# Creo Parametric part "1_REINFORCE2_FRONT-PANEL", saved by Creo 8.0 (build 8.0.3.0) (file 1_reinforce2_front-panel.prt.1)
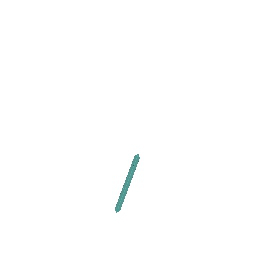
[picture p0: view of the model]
Units: millimeter Newton Second (mmNs); MM, TONNE, SECS

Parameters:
  SMT_DFLT_BEND_REL_LENGTH_TYPE = "Through All"

Other parameters: SMT_THICKNESS, SMT_PART_BEND_ALLOWANCE_FACTOR, SMT_DFLT_BEND_RADIUS, SMT_DFLT_BEND_ANGLE, SMT_DFLT_CRNR_REL_WIDTH, SMT_DFLT_CRNR_REL_DEPTH, SMT_DFLT_BEND_REL_WIDTH, SMT_DFLT_BEND_REL_DEPTH, SMT_DFLT_BEND_REL_LENGTH, SMT_DFLT_BEND_REL_ANGLE, SMT_GAP, SMT_DFLT_EDGE_TREA_WIDTH, SMT_DFLT_MITER_CUT_WIDTH, SMT_DFLT_MITER_CUT_OFFSET

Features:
  1. datum plane "DTM1"
  2. datum plane "DTM2"
  3. datum plane "DTM3"
  4. coordinate system
  5. protrusion
  6. round
  7. cut

Other named items: CS0

Layers: 0_ALL_AXIS, 0_ALL_CSYS, 0_ALL_CURVES, 0_ALL_PLANES, 0_ALL_POINTS, 0_ALL_SURFS, REINFORCE2_FRONT-PANEL

Surfaces: 24 plane, 12 cylinder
